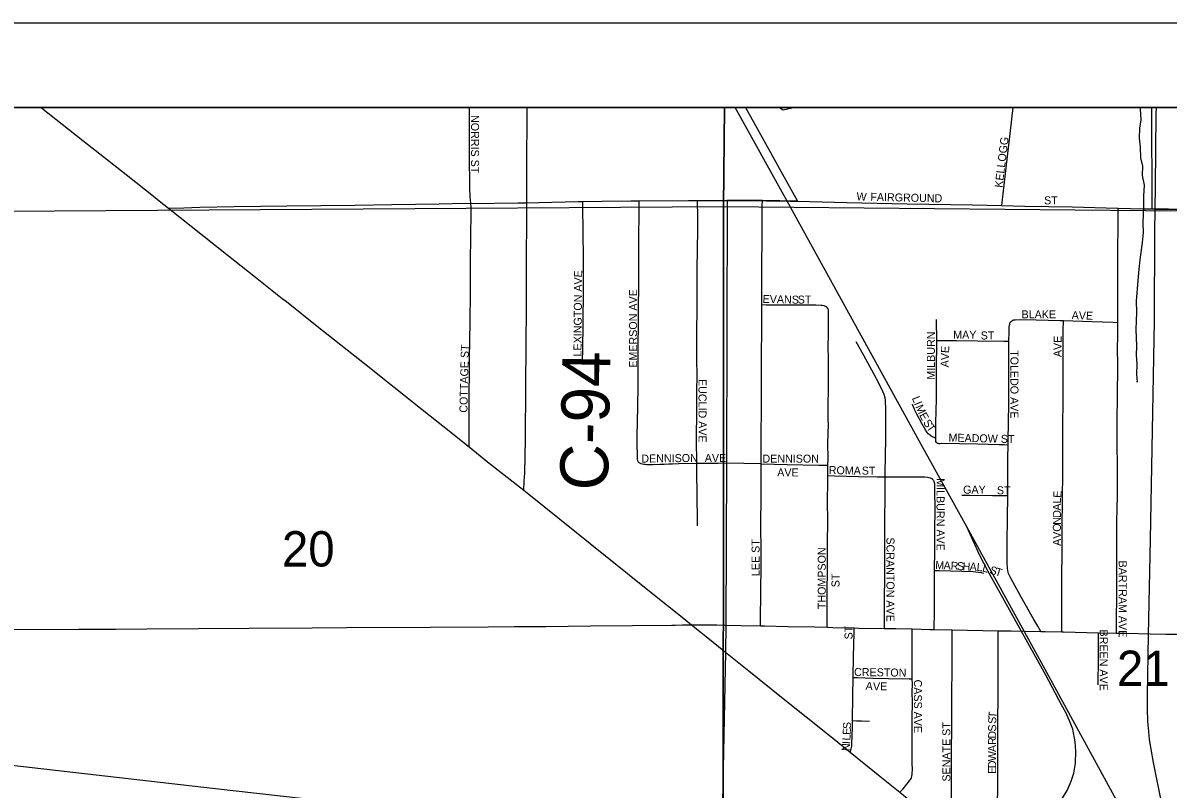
# Model space of a CAD drawing. Extents: x -9.1 to 34, y -3.1 to 22.
# Drawn here: x 3.4 to 4.755, y 20.093 to 21 of the extents above; entities that cross this region are included whole.
import ezdxf

# ---------------------------------------------------------------- set-up
doc = ezdxf.new("R2010")
doc.units = 0
for name, color, linetype in [('GM_X_City_Street', 7, 'Continuous'), ('GM_X_City_Street_Text', 7, 'Continuous'), ('GM_X_Corporation', 7, 'Continuous'), ('GM_X_County_Road', 7, 'Continuous'), ('GM_X_County_Road_Text', 7, 'Continuous'), ('GM_X_Minor_Lake', 7, 'Continuous'), ('GM_X_Minor_River', 7, 'Continuous'), ('GM_X_Rail_Line', 7, 'Continuous'), ('GM_X_Section', 7, 'Continuous'), ('GM_X_Section_Text', 7, 'Continuous'), ('GM_X_State_Route', 7, 'Continuous'), ('GM_X_Township_Subdivision', 7, 'Continuous'), ('GM_X_Township_Subdivision_Text', 7, 'Continuous'), ('SH_Data', 7, 'Continuous')]:
    doc.layers.add(name, color=color, linetype=linetype)

msp = doc.modelspace()

# ---------------------------------------------------------------- linework, layer by layer
at = {"layer": 'GM_X_City_Street'}
for points in [[(4.5585, 20.7837), (4.5589, 20.7875), (4.5599, 20.7978), (4.5637, 20.8321), (4.5686, 20.8722), (4.5718, 20.9)], [(4.2741, 20.6665), (4.2741, 20.6872), (4.2744, 20.7089), (4.2745, 20.7493), (4.2746, 20.7741), (4.2748, 20.7834), (4.2749, 20.7896)], [(4.3163, 20.7888), (4.3749, 20.7873), (4.4462, 20.7859), (4.5237, 20.7845), (4.5585, 20.7837)], [(4.5585, 20.7837), (4.5857, 20.7831), (4.6415, 20.7821), (4.6818, 20.7812), (4.696, 20.7808)], [(4.6955, 20.6455), (4.6955, 20.679), (4.6957, 20.6976), (4.6957, 20.7286), (4.6961, 20.7627), (4.6961, 20.7761), (4.696, 20.7808)], [(4.696, 20.7808), (4.7252, 20.78), (4.7361, 20.7797)], [(4.2735, 20.4779), (4.2735, 20.4793), (4.2735, 20.5134), (4.2739, 20.5413), (4.274, 20.5847), (4.2741, 20.6592), (4.2741, 20.6665)], [(4.2741, 20.6665), (4.2794, 20.6664), (4.3104, 20.6662), (4.3383, 20.6663), (4.3445, 20.666), (4.3458, 20.6659), (4.3475, 20.6656), (4.3485, 20.6651), (4.3492, 20.6648), (4.3503, 20.6641), (4.3516, 20.663)], [(4.3524, 20.4764), (4.3526, 20.4841), (4.3525, 20.5027), (4.353, 20.5245), (4.3529, 20.5306), (4.3528, 20.5337), (4.3529, 20.5523), (4.353, 20.5616), (4.353, 20.5771), (4.3531, 20.5864), (4.3532, 20.602), (4.3529, 20.6175), (4.3531, 20.6298), (4.353, 20.6359), (4.3531, 20.6388), (4.3531, 20.6419), (4.3531, 20.6448), (4.3532, 20.6571), (4.3532, 20.6586), (4.353, 20.6602), (4.3524, 20.6618), (4.3516, 20.663)], [(4.4813, 20.6241), (4.4812, 20.632), (4.4811, 20.6401), (4.481, 20.6467), (4.481, 20.6487)], [(4.5668, 20.6233), (4.5669, 20.6344), (4.567, 20.638), (4.567, 20.6394), (4.5672, 20.6406), (4.5673, 20.6422), (4.5676, 20.6433), (4.5679, 20.6449)], [(4.5679, 20.6449), (4.5692, 20.6466), (4.5702, 20.6474), (4.5714, 20.6481), (4.5726, 20.6484), (4.574, 20.6485), (4.5803, 20.6488), (4.5991, 20.6483), (4.6273, 20.6476), (4.6312, 20.6475)], [(4.6294, 20.279), (4.6294, 20.2858), (4.6294, 20.3217), (4.6295, 20.3403), (4.6297, 20.3771), (4.6298, 20.4042), (4.6303, 20.4345), (4.6305, 20.4692), (4.6306, 20.5307), (4.6308, 20.545), (4.631, 20.5719), (4.631, 20.5964), (4.6311, 20.64), (4.6312, 20.6431), (4.6312, 20.6475)], [(4.6312, 20.6475), (4.6649, 20.6465), (4.69, 20.6457), (4.6955, 20.6455)], [(4.694, 20.2777), (4.6941, 20.2859), (4.6946, 20.3294), (4.6946, 20.3635), (4.6946, 20.3791), (4.6944, 20.3854), (4.6945, 20.3879), (4.6945, 20.3968), (4.6946, 20.4093), (4.6951, 20.4403), (4.6951, 20.462), (4.695, 20.5148), (4.695, 20.5272), (4.6955, 20.5924), (4.6954, 20.6173), (4.6955, 20.6266), (4.6955, 20.6455)], [(4.4204, 20.4625), (4.4204, 20.4672), (4.4209, 20.5074), (4.421, 20.5259), (4.4209, 20.5444), (4.421, 20.5463), (4.4208, 20.5488), (4.4207, 20.5507), (4.4205, 20.5533), (4.4201, 20.5562), (4.4192, 20.5601), (4.4175, 20.5636), (4.4158, 20.5673), (4.4145, 20.5699), (4.4126, 20.5733), (4.4068, 20.5844), (4.395, 20.6062), (4.3874, 20.6198), (4.3859, 20.6225)], [(4.4801, 20.5082), (4.4802, 20.5096), (4.4802, 20.5108), (4.4803, 20.5141), (4.4802, 20.5266), (4.4808, 20.5548), (4.4808, 20.5924), (4.4813, 20.6205), (4.4813, 20.6241)], [(4.4813, 20.6241), (4.4862, 20.6241), (4.4924, 20.6241), (4.5048, 20.6241), (4.5297, 20.6236), (4.5607, 20.6233), (4.5668, 20.6233)], [(4.5659, 20.5006), (4.566, 20.5089), (4.5663, 20.5243), (4.5666, 20.552), (4.5667, 20.5696), (4.5668, 20.6158), (4.5668, 20.6233)], [(4.4801, 20.5082), (4.477, 20.5094), (4.4747, 20.5107), (4.4722, 20.5127), (4.4713, 20.5136), (4.4701, 20.515), (4.4683, 20.5175), (4.4637, 20.5257), (4.4579, 20.5369), (4.455, 20.5424), (4.4538, 20.5453), (4.4527, 20.5482), (4.4526, 20.5487)], [(4.4817, 20.5026), (4.4809, 20.5033), (4.4804, 20.5045), (4.4802, 20.5057), (4.4801, 20.5082)], [(4.4817, 20.5026), (4.4823, 20.5024), (4.4828, 20.5023), (4.4834, 20.5022), (4.4841, 20.5022), (4.4852, 20.5022), (4.4869, 20.5023), (4.5081, 20.5021), (4.53, 20.5017), (4.555, 20.5008), (4.5612, 20.5007), (4.5659, 20.5006)], [(4.5654, 20.4405), (4.5655, 20.447), (4.5656, 20.4842), (4.5659, 20.5006)], [(4.2735, 20.4779), (4.2325, 20.4786)], [(4.2728, 20.2861), (4.2728, 20.2939), (4.2729, 20.325), (4.2734, 20.3591), (4.2733, 20.3746), (4.273, 20.4055), (4.2731, 20.4148), (4.2734, 20.4302), (4.2735, 20.4609), (4.2735, 20.4779)], [(4.2735, 20.4779), (4.3043, 20.4773), (4.3416, 20.4765), (4.3478, 20.4764), (4.3524, 20.4764)], [(4.3523, 20.4641), (4.3523, 20.4716), (4.3524, 20.4764)], [(4.3514, 20.2845), (4.3515, 20.2912), (4.3517, 20.2975), (4.3514, 20.3223), (4.352, 20.3565), (4.3519, 20.3783), (4.3522, 20.4156), (4.3521, 20.4281), (4.3523, 20.4623), (4.3523, 20.4641)], [(4.3523, 20.4641), (4.3603, 20.4639), (4.3886, 20.4631), (4.4106, 20.4626), (4.4175, 20.4626), (4.4204, 20.4625)], [(4.4193, 20.2831), (4.4193, 20.2907), (4.4198, 20.3712), (4.4199, 20.4177), (4.4203, 20.4332), (4.4204, 20.4548), (4.4204, 20.4625)], [(4.4204, 20.4625), (4.4483, 20.4625), (4.4672, 20.4624), (4.4703, 20.4622), (4.4718, 20.462), (4.4734, 20.4615), (4.475, 20.4607)], [(4.4787, 20.3517), (4.4787, 20.353), (4.479, 20.3746), (4.4792, 20.3839), (4.4791, 20.3906), (4.4789, 20.3963), (4.4793, 20.4273), (4.4792, 20.4429), (4.4792, 20.4522), (4.4792, 20.4529), (4.4791, 20.4536), (4.479, 20.4545), (4.4787, 20.4553), (4.4784, 20.4566), (4.4781, 20.4574), (4.4776, 20.4581), (4.477, 20.459), (4.4763, 20.4598), (4.475, 20.4607)], [(4.511, 20.4408), (4.52, 20.4408), (4.5474, 20.4404), (4.5594, 20.4404), (4.5654, 20.4405)], [(4.6044, 20.2795), (4.6008, 20.2858), (4.5961, 20.2938), (4.581, 20.3209), (4.569, 20.3426), (4.5664, 20.3483), (4.5654, 20.3514), (4.5649, 20.3545), (4.5646, 20.3608), (4.5645, 20.3731), (4.5646, 20.3855), (4.5651, 20.4131), (4.5654, 20.4405)], [(4.4782, 20.2819), (4.4783, 20.2879), (4.4785, 20.2971), (4.4786, 20.3097), (4.4785, 20.3159), (4.4786, 20.3221), (4.4785, 20.3283), (4.4786, 20.3375), (4.4786, 20.3406), (4.4786, 20.3437), (4.4786, 20.3498), (4.4787, 20.3517)], [(4.4787, 20.3517), (4.484, 20.3516), (4.5245, 20.3504), (4.5307, 20.3499), (4.5338, 20.3495), (4.5368, 20.3486)], [(4.2315, 20.287), (4.2495, 20.2867), (4.2728, 20.2861)], [(4.2728, 20.2861), (4.2775, 20.286), (4.3054, 20.2855), (4.3364, 20.285), (4.3514, 20.2845)], [(4.3514, 20.2845), (4.3581, 20.2843), (4.3836, 20.2837)], [(4.3824, 20.2251), (4.3828, 20.2499), (4.3834, 20.2777), (4.3836, 20.2837)], [(4.3836, 20.2837), (4.3892, 20.2835), (4.4193, 20.2831)], [(4.4193, 20.2831), (4.4327, 20.2829), (4.4522, 20.2825)], [(4.4523, 20.2233), (4.4521, 20.2511), (4.452, 20.2635), (4.4522, 20.2758), (4.4522, 20.2825)], [(4.4522, 20.2825), (4.473, 20.282), (4.4782, 20.2819)], [(4.4782, 20.2819), (4.4996, 20.2815)], [(4.4987, 20.0552), (4.4988, 20.0584), (4.4989, 20.0614), (4.4986, 20.0832), (4.4988, 20.1175), (4.499, 20.186), (4.4994, 20.2546), (4.4995, 20.2764), (4.4996, 20.2815)], [(4.4996, 20.2815), (4.5538, 20.2804), (4.5541, 20.2804)], [(4.5514, 20.0563), (4.5522, 20.0575), (4.5527, 20.0588), (4.553, 20.0602), (4.5531, 20.0621), (4.5532, 20.0645), (4.5532, 20.0683), (4.5533, 20.0776), (4.5534, 20.093), (4.5537, 20.1269), (4.5537, 20.1516), (4.5537, 20.1748), (4.5538, 20.2012), (4.5539, 20.2242), (4.5539, 20.2426), (4.554, 20.2572), (4.554, 20.2725), (4.5541, 20.2804)], [(4.5541, 20.2804), (4.5693, 20.2802), (4.5849, 20.28), (4.6044, 20.2795)], [(4.6044, 20.2795), (4.6097, 20.2794), (4.6294, 20.279)], [(4.6294, 20.279), (4.6315, 20.279), (4.6729, 20.2781)], [(4.6724, 20.2165), (4.6726, 20.2473), (4.6728, 20.2719), (4.6729, 20.2781)], [(4.6729, 20.2781), (4.694, 20.2777)], [(4.694, 20.2777), (4.7058, 20.2774), (4.7337, 20.2768), (4.7523, 20.2764), (4.7667, 20.2762)], [(4.3816, 20.1741), (4.382, 20.2034), (4.3824, 20.2251)], [(4.3824, 20.2251), (4.3873, 20.2249), (4.3965, 20.2247), (4.4055, 20.2244), (4.4238, 20.2239), (4.4485, 20.2234), (4.4523, 20.2233)], [(4.4377, 20.0892), (4.4414, 20.0934), (4.4458, 20.0986), (4.448, 20.1013), (4.4496, 20.1033), (4.4503, 20.1042), (4.4509, 20.1053), (4.4515, 20.1066), (4.4519, 20.1081), (4.4521, 20.1101), (4.4523, 20.1121), (4.4524, 20.1152), (4.4522, 20.1244), (4.4522, 20.143), (4.4521, 20.1584), (4.4521, 20.177), (4.4524, 20.1955), (4.4523, 20.2079), (4.4524, 20.2171), (4.4523, 20.2233)], [(4.3789, 20.1366), (4.38, 20.1406), (4.3806, 20.1438), (4.3808, 20.1466), (4.3815, 20.1662), (4.3816, 20.1741)], [(4.3816, 20.1741), (4.3863, 20.1739), (4.3924, 20.1737), (4.4017, 20.1733)]]:
    msp.add_lwpolyline(points, dxfattribs=at)
at = {"layer": 'GM_X_Corporation'}
msp.add_line((4.736, 20.9), (4.2551, 20.9), dxfattribs=at)
for points in [[(4.2551, 20.9), (4.3163, 20.7888), (4.2749, 20.7896), (4.2334, 20.7897), (4.2325, 20.4786), (4.2315, 20.287), (4.2311, 20.2552), (4.2261, 19.9988)], [(5.0413, 20.9), (5.0407, 20.7738), (5.0219, 20.774), (5.0216, 20.877), (5.0056, 20.877), (5.0062, 20.7743), (4.9832, 20.7748), (4.909, 20.7764), (4.7361, 20.7797), (4.736, 20.9)]]:
    msp.add_lwpolyline(points, dxfattribs=at)
at = {"layer": 'GM_X_County_Road'}
for points in [[(3.9961, 20.7871), (3.9961, 20.8136), (3.9963, 20.8402), (3.9966, 20.8835), (3.9965, 20.9)], [(3.5718, 20.7808), (3.5903, 20.7812), (3.6092, 20.7817), (3.6497, 20.7825), (3.7119, 20.7833), (3.7927, 20.7843), (3.8363, 20.7852), (3.8923, 20.7858), (3.9234, 20.7864), (3.9298, 20.7863)], [(3.9298, 20.7863), (3.9856, 20.7869), (3.9961, 20.7871)], [(3.9924, 20.4469), (3.9931, 20.4575), (3.9938, 20.4668), (3.9945, 20.5072), (3.9951, 20.5694), (3.9953, 20.6192), (3.9958, 20.6627), (3.9958, 20.7062), (3.9961, 20.7817), (3.9961, 20.7871)], [(3.9961, 20.7871), (4.0104, 20.7872), (4.057, 20.7884), (4.0622, 20.7885)], [(4.0622, 20.7885), (4.085, 20.7888), (4.1192, 20.7895), (4.1289, 20.7895)], [(4.1289, 20.7895), (4.1876, 20.7899), (4.198, 20.7898)], [(4.198, 20.7898), (4.2334, 20.7897)], [(4.2334, 20.7897), (4.264, 20.7897), (4.2749, 20.7896)], [(4.2749, 20.7896), (4.2796, 20.7895), (4.2952, 20.7893), (4.3077, 20.789), (4.3163, 20.7888)], [(4.7361, 20.7797), (4.7405, 20.7795), (4.7716, 20.7791), (4.8309, 20.778), (4.9058, 20.7764), (4.909, 20.7764)], [(3.2478, 20.2825), (3.2855, 20.2824), (3.3849, 20.2819), (3.4657, 20.2822), (3.5092, 20.2824), (3.5465, 20.2825), (3.6676, 20.2834), (3.7422, 20.2839), (3.7826, 20.2841), (3.882, 20.2846), (3.9503, 20.2852), (3.9814, 20.2856), (4.0186, 20.2856), (4.0714, 20.2861), (4.1211, 20.2865), (4.1676, 20.2869), (4.1717, 20.287), (4.1804, 20.2872), (4.191, 20.2875)], [(4.191, 20.2875), (4.2023, 20.2875), (4.2094, 20.2874), (4.2208, 20.2873), (4.2315, 20.287)]]:
    msp.add_lwpolyline(points, dxfattribs=at)
at = {"layer": 'GM_X_Minor_Lake'}
msp.add_lwpolyline([(4.2952, 20.9), (4.2997, 20.897), (4.3099, 20.8995), (4.3126, 20.9)], dxfattribs=at)
at = {"layer": 'GM_X_Minor_River'}
msp.add_lwpolyline([(4.722, 20.9), (4.722, 20.8981), (4.7229, 20.8852), (4.7213, 20.8753), (4.7207, 20.8636), (4.722, 20.8529), (4.7226, 20.8404), (4.7247, 20.8302), (4.7245, 20.8195), (4.7269, 20.8077), (4.726, 20.7949), (4.7261, 20.7831), (4.7256, 20.7733), (4.7254, 20.7634), (4.7256, 20.752), (4.7243, 20.7399), (4.7217, 20.7195), (4.7204, 20.7085), (4.7194, 20.6949), (4.7175, 20.6707), (4.7176, 20.657), (4.7175, 20.6472), (4.7169, 20.637), (4.7177, 20.6172), (4.7172, 20.6066), (4.7181, 20.5964), (4.7179, 20.5842), (4.7185, 20.5748), (4.7182, 20.5755)], dxfattribs=at)
at = {"layer": 'GM_X_Rail_Line'}
for points in [[(4.5167, 20.4033), (4.4649, 20.4974), (4.3043, 20.7888), (4.2428, 20.9)], [(4.7549, 20.04), (4.7482, 20.0738), (4.7411, 20.1087), (4.7379, 20.1244), (4.7349, 20.1403), (4.7332, 20.1517), (4.7322, 20.1612), (4.7311, 20.1733), (4.7307, 20.1876), (4.7309, 20.2038), (4.7318, 20.2757), (4.7341, 20.3885), (4.739, 20.647), (4.7394, 20.7523), (4.7401, 20.8069), (4.7411, 20.8916), (4.7412, 20.9)], [(4.4598, 20.0243), (4.5317, 20.0341), (4.5565, 20.037), (4.5709, 20.0401), (4.5832, 20.0441), (4.5936, 20.0487), (4.6042, 20.0551), (4.613, 20.0618), (4.6222, 20.0714), (4.6295, 20.0809), (4.6358, 20.0914), (4.6404, 20.1022), (4.6434, 20.1116), (4.6456, 20.1235), (4.6461, 20.138), (4.6452, 20.1487), (4.6425, 20.1637), (4.6386, 20.1737), (4.634, 20.1837), (4.6291, 20.1926), (4.6103, 20.2278), (4.5423, 20.3507), (4.5318, 20.3704), (4.5167, 20.4033)], [(4.6114, 20.2311), (4.5852, 20.2789), (4.5167, 20.4033)], [(4.7097, 20.0387), (4.7021, 20.0613), (4.6964, 20.0753), (4.6114, 20.2311)], [(2.6, 20.2062), (2.6188, 20.2048), (2.6502, 20.2037), (2.671, 20.2028), (2.7079, 20.1988), (3.6242, 20.0941), (3.9983, 20.0517), (4.1941, 20.0298), (4.219, 20.0279), (4.2423, 20.0262), (4.2931, 20.0256), (4.3579, 20.026), (4.3853, 20.0269), (4.4001, 20.0265), (4.4445, 20.0235)]]:
    msp.add_lwpolyline(points, dxfattribs=at)
at = {"layer": 'GM_X_Section'}
for p, q in [((4.2302, 20.9), (3.2563, 20.9)), ((5.2292, 20.9), (4.2302, 20.9))]:
    msp.add_line(p, q, dxfattribs=at)
for points in [[(3.2563, 20.9), (3.2541, 20.7764), (4.2289, 20.7827), (4.2302, 20.9)], [(4.2302, 20.9), (4.2289, 20.7827), (5.2279, 20.7732), (5.2292, 20.9)]]:
    msp.add_lwpolyline(points, dxfattribs=at)
for points in [[(3.2541, 20.7764), (4.2289, 20.7827), (4.2285, 19.7772), (3.2347, 19.7726)], [(4.2289, 20.7827), (5.2279, 20.7732), (5.226, 19.7723), (4.2285, 19.7772)]]:
    msp.add_lwpolyline(points, close=True, dxfattribs=at)
at = {"layer": 'GM_X_State_Route'}
for points in [[(3.4208, 20.9), (3.4217, 20.8993), (3.4704, 20.8606), (3.5218, 20.8205), (3.5561, 20.7932)], [(3.5561, 20.7932), (3.5608, 20.7895), (3.5718, 20.7808)], [(3.5718, 20.7808), (3.6412, 20.726), (3.675, 20.6991), (3.7067, 20.6739), (3.7115, 20.6701), (3.748, 20.641), (3.804, 20.5967), (3.8721, 20.5425), (3.8988, 20.5212), (3.9277, 20.4981), (3.9497, 20.4804), (3.9924, 20.4469), (3.9985, 20.442), (4.0712, 20.3835), (4.1414, 20.3271), (4.1819, 20.2948), (4.191, 20.2875), (4.2025, 20.2782), (4.2084, 20.2734), (4.2311, 20.2552)], [(4.2311, 20.2552), (4.259, 20.2329), (4.2977, 20.2017), (4.3559, 20.1551), (4.3789, 20.1366), (4.414, 20.1083), (4.4377, 20.0892), (4.4527, 20.0771), (4.4722, 20.0617), (4.4829, 20.0533), (4.4979, 20.0414), (4.5058, 20.035), (4.5127, 20.0295), (4.52, 20.0237), (4.5233, 20.0212), (4.5286, 20.0172), (4.541, 20.0085), (4.5614, 19.9947), (4.572, 19.9878), (4.5783, 19.9837), (4.5825, 19.9806), (4.5859, 19.9776)]]:
    msp.add_lwpolyline(points, dxfattribs=at)
at = {"layer": 'GM_X_Township_Subdivision'}
for points in [[(3.9298, 20.7863), (3.9293, 20.7909), (3.929, 20.7942), (3.9285, 20.8042), (3.9284, 20.8443), (3.9282, 20.897), (3.9281, 20.9)], [(3.9277, 20.4981), (3.9277, 20.5075), (3.9278, 20.5438), (3.9281, 20.6027), (3.929, 20.6461), (3.9294, 20.6802), (3.9294, 20.7175), (3.9301, 20.7759), (3.9301, 20.7821), (3.9298, 20.7863)], [(4.062, 20.5993), (4.0623, 20.6147), (4.0628, 20.6425), (4.0632, 20.6857), (4.0632, 20.7074), (4.0631, 20.7197), (4.0629, 20.7537), (4.0624, 20.7815), (4.0622, 20.7885)], [(4.1278, 20.4804), (4.1274, 20.4821), (4.1272, 20.4837), (4.127, 20.4869), (4.127, 20.4898), (4.1267, 20.499), (4.1268, 20.5111), (4.1274, 20.5453), (4.1278, 20.5702), (4.128, 20.6044), (4.128, 20.6226), (4.1281, 20.6384), (4.1281, 20.6602), (4.1285, 20.6913), (4.1287, 20.7255), (4.1288, 20.7566), (4.129, 20.7637), (4.1291, 20.7721), (4.129, 20.7814), (4.1289, 20.7895)], [(4.1972, 20.4782), (4.197, 20.5069), (4.1972, 20.541), (4.1974, 20.5565), (4.1974, 20.5596), (4.1976, 20.5874), (4.1975, 20.5967), (4.1975, 20.6123), (4.1975, 20.6371), (4.1978, 20.6588), (4.1978, 20.7084), (4.1986, 20.7549), (4.1984, 20.7766), (4.1982, 20.7828), (4.198, 20.7898)], [(4.1972, 20.4782), (4.1762, 20.4779), (4.1687, 20.4776), (4.1642, 20.4775), (4.1586, 20.4773), (4.1539, 20.4772), (4.1454, 20.4769), (4.1423, 20.4768), (4.1383, 20.4769), (4.1362, 20.477), (4.1346, 20.4772), (4.1331, 20.4775), (4.1316, 20.4779), (4.1307, 20.4783), (4.1298, 20.4787), (4.129, 20.4793), (4.1278, 20.4804)], [(4.2325, 20.4786), (4.2224, 20.4785), (4.1972, 20.4782)], [(4.198, 20.4105), (4.1973, 20.4697), (4.1972, 20.4782)], [(4.1981, 20.4045), (4.198, 20.4105)]]:
    msp.add_lwpolyline(points, dxfattribs=at)
at = {"layer": 'SH_Data'}
for p, q in [((2.5, 21), (9.5, 21)), ((2.6, 20.9), (9.4, 20.9))]:
    msp.add_line(p, q, dxfattribs=at)

# ---------------------------------------------------------------- texts
at = {"layer": 'GM_X_City_Street_Text'}
for s, rotation, p in [('KELLOGG', 83.0895, (4.5591, 20.8045)), ('W', 355.6039, (4.386, 20.7902)), ('FAIRGROUND', 358.7392, (4.4026, 20.7894)), ('ST', 0, (4.6083, 20.7852)), ('EVANS', 358.7243, (4.2751, 20.6685)), ('ST', 0, (4.3167, 20.6677)), ('BLAKE', 0, (4.5817, 20.6502)), ('AVE', 358.0264, (4.6409, 20.6494)), ('MILBURN', 90, (4.4791, 20.5776)), ('MAY', 0, (4.5008, 20.626)), ('ST', 0, (4.5333, 20.6252)), ('AVE', 88.0918, (4.4953, 20.5921)), ('AVE', 90, (4.6291, 20.6043)), ('TOLEDO AVE', 270, (4.5685, 20.6126)), ('L', 292.5421, (4.4517, 20.5557)), ('I', 292.6003, (4.4542, 20.5495)), ('M', 293.3806, (4.4559, 20.5456)), ('E', 297.7847, (4.4602, 20.5357)), ('S', 300.5795, (4.4648, 20.5271)), ('T', 305.0375, (4.4686, 20.5207)), ('MEADOW ST', 358.6182, (4.4951, 20.5044)), ('DENNISON', 0, (4.275, 20.4794)), ('AVE', 0, (4.2925, 20.4631)), ('ROMA', 358.6368, (4.3534, 20.466)), ('ST', 0, (4.3925, 20.4652)), ('MILBURN AVE', 270, (4.481, 20.4609)), ('GAY', 0, (4.5125, 20.4427)), ('ST', 0, (4.5525, 20.4419)), ('E', 86.1168, (4.6285, 20.4374)), ('L', 88.0053, (4.6282, 20.4308)), ('A', 89.9781, (4.6282, 20.4226)), ('D', 89.9781, (4.6282, 20.4142)), ('N', 89.9781, (4.6282, 20.4059)), ('O', 89.9928, (4.6282, 20.3976)), ('LEE ST', 90, (4.2716, 20.3451)), ('SCRANTON AVE', 270, (4.4218, 20.3909)), ('V', 89.9781, (4.6282, 20.3893)), ('A', 89.9781, (4.6282, 20.3809)), ('THOMPSON', 90, (4.3499, 20.3059)), ('M', 357.3395, (4.4793, 20.3535)), ('A', 357.3329, (4.4892, 20.3531)), ('R', 357.328, (4.4976, 20.3527)), ('S', 357.3218, (4.5051, 20.3523)), ('H', 357.3357, (4.5117, 20.352)), ('A', 357.3329, (4.52, 20.3516)), ('L', 354.4172, (4.5282, 20.3513)), ('L', 345.4734, (4.5345, 20.3507)), ('BARTRAM AVE', 270, (4.6968, 20.3634)), ('ST', 90, (4.3662, 20.3318)), ('S', 342.7747, (4.5432, 20.3483)), ('T', 342.7486, (4.5496, 20.3463)), ('ST', 90, (4.3816, 20.2701)), ('BREEN AVE', 270, (4.6743, 20.2818)), ('CRESTON', 359.1039, (4.3834, 20.2269)), ('A', 355.2509, (4.3968, 20.2107)), ('V', 358.7542, (4.4057, 20.2099)), ('E', 359.9208, (4.4143, 20.2098)), ('CASS AVE', 270, (4.4543, 20.2226)), ('T', 85.4882, (4.5518, 20.1766)), ('S', 88.9146, (4.3797, 20.1639)), ('SENATE ST', 90, (4.4974, 20.1018)), ('S', 88.3603, (4.5516, 20.17)), ('L', 86.6446, (4.379, 20.1502)), ('E', 86.7968, (4.3793, 20.1568)), ('S', 90, (4.5516, 20.1609)), ('D', 89.9812, (4.5516, 20.1526)), ('N', 86.6541, (4.3782, 20.1377)), ('I', 86.6442, (4.3787, 20.146)), ('R', 89.9757, (4.5516, 20.1451)), ('A', 89.9781, (4.5516, 20.1368)), ('W', 89.9832, (4.5516, 20.1259)), ('D', 89.9812, (4.5516, 20.1176)), ('E', 89.9727, (4.5516, 20.1109))]:
    msp.add_text(s, height=0.00947, rotation=rotation, dxfattribs=at).set_placement(p)
at = {"layer": 'GM_X_County_Road_Text'}
msp.add_text('C-94', height=0.05682, rotation=88.9861, dxfattribs=at).set_placement((4.0921, 20.4462))
at = {"layer": 'GM_X_Section_Text'}
for s, p in [('20', (3.7063, 20.3564)), ('21', (4.6946, 20.215))]:
    msp.add_text(s, height=0.04186, rotation=0, dxfattribs=at).set_placement(p)
at = {"layer": 'GM_X_Township_Subdivision_Text'}
for s, rotation, p in [('NORRIS ST', 270, (3.9301, 20.8909)), ('LEXINGTON AVE', 89.4819, (4.0607, 20.6051)), ('EMERSON AVE', 90, (4.1266, 20.5918)), ('COTTAGE ST', 88.6549, (3.9257, 20.5384)), ('EUCLID AVE', 270, (4.1993, 20.5784)), ('DENNISON', 0.7965, (4.1317, 20.4794)), ('AVE', 0, (4.2067, 20.4802))]:
    msp.add_text(s, height=0.00947, rotation=rotation, dxfattribs=at).set_placement(p)

doc.saveas('drawing.dxf')
